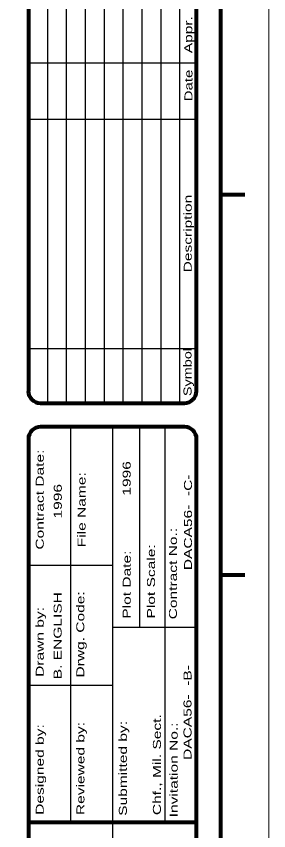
# Model space of a CAD drawing. Extents: x 55 to 190, y 198 to 264.
# Drawn here: x 140.29 to 146.59, y 221.76 to 242.12 of the extents above; entities that cross this region are included whole.
import ezdxf

# ---------------------------------------------------------------- set-up
doc = ezdxf.new("R2010")
doc.units = 0
doc.header["$LTSCALE"] = 0.1
doc.layers.add('1', color=7, linetype='Continuous', lineweight=25)
doc.layers.add('3', color=7, linetype='Continuous', lineweight=25)

msp = doc.modelspace()

# ---------------------------------------------------------------- linework, layer by layer
at = {"layer": '1'}
for p, q in [((141.0665, 251.8525), (141.0665, 232.4525)), ((141.5377, 251.8525), (141.5377, 232.4525)), ((142.009, 251.8525), (142.009, 232.4525)), ((142.4815, 251.8525), (142.4815, 232.4525)), ((142.9527, 251.8525), (142.9527, 232.4525)), ((143.4252, 251.8525), (143.4252, 232.4525)), ((143.8965, 251.8525), (143.8965, 232.4525)), ((144.3677, 251.8525), (144.3677, 232.4525)), ((140.5902, 240.9525), (144.7902, 240.9525)), ((140.5902, 239.5475), (144.7902, 239.5475)), ((140.5902, 233.8137), (144.7902, 233.8137)), ((141.6427, 231.855), (141.6427, 221.9637)), ((142.6927, 231.855), (142.6927, 215.4537)), ((143.3627, 231.855), (143.3627, 226.8512)), ((143.999, 231.855), (143.999, 221.9637)), ((142.6927, 228.3937), (140.5927, 228.3937)), ((142.6927, 226.8512), (144.7927, 226.8512)), ((140.5952, 225.3962), (142.6927, 225.3962))]:
    msp.add_line(p, q, dxfattribs=at)
at = {"layer": '1', "lineweight": 80}
for p, q in [((140.5902, 251.5525), (140.5902, 232.7525)), ((144.7902, 232.7525), (144.7902, 251.5525)), ((145.9927, 237.6525), (145.3927, 237.6525)), ((140.8902, 232.4525), (144.4902, 232.4525)), ((144.4927, 231.855), (140.8927, 231.855)), ((140.5927, 231.555), (140.5927, 215.7537)), ((144.7927, 215.7537), (144.7927, 231.555)), ((145.9927, 228.1525), (145.3927, 228.1525)), ((144.7927, 221.9637), (140.5927, 221.9637))]:
    msp.add_line(p, q, dxfattribs=at)
at = {"layer": '1', "lineweight": 13}
msp.add_lwpolyline([(62.4915, 257.8525), (146.5927, 257.8525), (146.5927, 198.4512), (62.4915, 198.4512)], close=True, dxfattribs=at)
at = {"layer": '1', "lineweight": 80}
msp.add_lwpolyline([(65.1915, 256.6525), (145.3927, 256.6525), (145.3927, 199.6512), (65.1915, 199.6512)], close=True, dxfattribs=at)
for centre, start, end in [((140.89, 232.7519), 180, 270), ((144.4899, 232.7519), 270, 0), ((140.8922, 231.5539), 90, 180), ((144.4922, 231.5539), 0, 90)]:
    msp.add_arc(centre, 0.3, start, end, dxfattribs=at)

# ---------------------------------------------------------------- texts
at = {"layer": '1'}
for s, width, p in [('Appr.', 1.45, (144.684, 241.195)), ('Date', 1.4, (144.689, 239.9937)), ('Description', 1.45, (144.6702, 235.7175)), ('Symbol', 1.35, (144.6652, 232.625)), ('Contract Date:', 1.45, (140.9752, 228.7887)), ('File Name:', 1.45, (142.019, 228.8475)), ('DACA56-  -C-    ', 1.45, (144.6777, 228.2737)), ('       1996', 1.45, (141.4252, 228.8112)), ('Contract No.:', 1.45, (144.3015, 227.0462)), ('Plot Scale:', 1.45, (143.754, 227.0675)), ('Plot Date:', 1.45, (143.1465, 227.0625)), ('Drwg. Code:', 1.45, (141.9877, 225.5912)), ('Drawn by:', 1.45, (140.9752, 225.6075)), ('DACA56-  -B-    ', 1.45, (144.6652, 223.5325)), ('Chf., Mil. Sect.', 1.45, (143.9015, 222.1525)), ('Designed by:', 1.45, (140.9752, 222.16)), ('Reviewed by:', 1.45, (141.9915, 222.1525)), ('Submitted by:', 1.45, (143.0502, 222.135)), ('Invitation No.:', 1.45, (144.319, 222.0975))]:
    msp.add_text(s, height=0.2, rotation=90, dxfattribs=dict(at, width=width)).set_placement(p)
at = {"layer": '3', "width": 1.45}
for s, p in [('       1996', (143.1452, 229.3825)), ('B. ENGLISH  ', (141.4215, 225.5487))]:
    msp.add_text(s, height=0.2, rotation=90, dxfattribs=at).set_placement(p)

doc.saveas('drawing.dxf')
